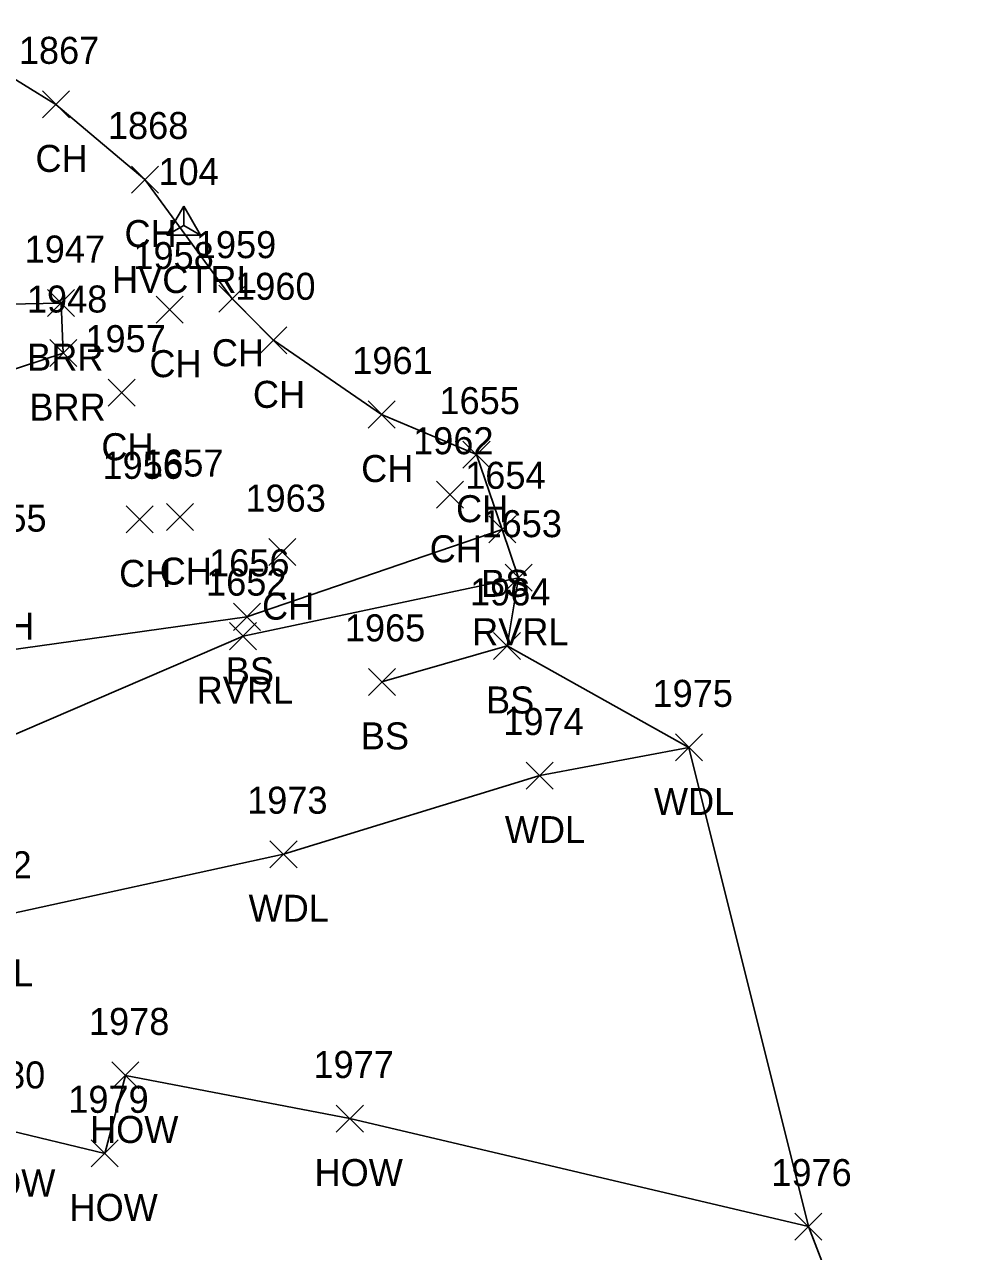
# Model space of a CAD drawing. Extents: x 1616726 to 1619875, y 273782 to 276557.
# Drawn here: x 1617145 to 1617213.9, y 276234.9 to 276325.7 of the extents above; entities that cross this region are included whole.
import ezdxf

# ---------------------------------------------------------------- set-up
doc = ezdxf.new("R2010")
doc.units = 0
for name, color, linetype in [('C_A', 7, 'Continuous'), ('C_I', 7, 'Continuous'), ('CPSM', 7, 'Continuous'), ('L_A', 7, 'Continuous'), ('L_I', 7, 'Continuous'), ('L_TIC', 7, 'Continuous'), ('LABL', 7, 'Continuous'), ('LAWA', 7, 'Continuous'), ('LAWE', 7, 'Continuous'), ('LBC', 7, 'Continuous'), ('LELB', 7, 'Continuous'), ('LSOGP', 7, 'Continuous')]:
    doc.layers.add(name, color=color, linetype=linetype)

msp = doc.modelspace()

# ---------------------------------------------------------------- linework, layer by layer
at = {"layer": 'CPSM'}
for p, q in [((1617155.513, 276310.096), (1617156.763, 276312.261)), ((1617155.513, 276310.096), (1617156.763, 276312.261)), ((1617158.013, 276310.096), (1617156.763, 276312.261)), ((1617156.763, 276310.817), (1617156.763, 276312.261)), ((1617158.013, 276310.096), (1617156.763, 276312.261)), ((1617156.763, 276310.817), (1617156.763, 276312.261)), ((1617155.513, 276310.096), (1617156.763, 276310.817)), ((1617155.513, 276310.096), (1617156.763, 276310.817)), ((1617155.513, 276310.096), (1617158.013, 276310.096)), ((1617155.513, 276310.096), (1617158.013, 276310.096)), ((1617156.763, 276310.817), (1617156.763, 276310.817)), ((1617156.763, 276310.817), (1617158.013, 276310.096)), ((1617156.763, 276310.817), (1617156.763, 276310.817)), ((1617156.763, 276310.817), (1617158.013, 276310.096))]:
    msp.add_line(p, q, dxfattribs=at)
at = {"layer": 'L_TIC'}
for points in [[(1617146.301, 276318.786), (1617148.301, 276320.786)], [(1617148.301, 276318.786), (1617146.301, 276320.786)], [(1617152.89, 276313.221), (1617154.89, 276315.221)], [(1617154.89, 276313.221), (1617152.89, 276315.221)], [(1617159.356, 276304.401), (1617161.356, 276306.401)], [(1617161.356, 276304.401), (1617159.356, 276306.401)], [(1617146.684, 276304.076), (1617148.684, 276306.076)], [(1617148.684, 276304.076), (1617146.684, 276306.076)], [(1617154.729, 276303.591), (1617156.729, 276305.591)], [(1617156.729, 276303.591), (1617154.729, 276305.591)], [(1617162.391, 276301.319), (1617164.391, 276303.319)], [(1617164.391, 276301.319), (1617162.391, 276303.319)], [(1617146.851, 276300.376), (1617148.851, 276302.376)], [(1617148.851, 276300.376), (1617146.851, 276302.376)], [(1617151.177, 276297.443), (1617153.177, 276299.443)], [(1617153.177, 276297.443), (1617151.177, 276299.443)], [(1617170.402, 276295.827), (1617172.402, 276297.827)], [(1617172.402, 276295.827), (1617170.402, 276297.827)], [(1617177.422, 276292.855), (1617179.422, 276294.855)], [(1617179.422, 276292.855), (1617177.422, 276294.855)], [(1617175.472, 276289.885), (1617177.472, 276291.885)], [(1617177.472, 276289.885), (1617175.472, 276291.885)], [(1617152.493, 276288.064), (1617154.493, 276290.064)], [(1617154.493, 276288.064), (1617152.493, 276290.064)], [(1617155.493, 276288.235), (1617157.493, 276290.235)], [(1617157.493, 276288.235), (1617155.493, 276290.235)], [(1617179.325, 276287.326), (1617181.325, 276289.326)], [(1617181.325, 276287.326), (1617179.325, 276289.326)], [(1617163.067, 276285.639), (1617165.067, 276287.639)], [(1617165.067, 276285.639), (1617163.067, 276287.639)], [(1617180.534, 276283.745), (1617182.534, 276285.745)], [(1617182.534, 276283.745), (1617180.534, 276285.745)], [(1617160.431, 276280.848), (1617162.431, 276282.848)], [(1617162.431, 276280.848), (1617160.431, 276282.848)], [(1617160.153, 276279.417), (1617162.153, 276281.417)], [(1617162.153, 276279.417), (1617160.153, 276281.417)], [(1617179.684, 276278.693), (1617181.684, 276280.693)], [(1617181.684, 276278.693), (1617179.684, 276280.693)], [(1617170.422, 276276.034), (1617172.422, 276278.034)], [(1617172.422, 276276.034), (1617170.422, 276278.034)], [(1617193.136, 276271.184), (1617195.136, 276273.184)], [(1617195.136, 276271.184), (1617193.136, 276273.184)], [(1617182.103, 276269.097), (1617184.103, 276271.097)], [(1617184.103, 276269.097), (1617182.103, 276271.097)], [(1617163.142, 276263.272), (1617165.142, 276265.272)], [(1617165.142, 276263.272), (1617163.142, 276265.272)], [(1617151.443, 276246.898), (1617153.443, 276248.898)], [(1617153.443, 276246.898), (1617151.443, 276248.898)], [(1617168.05, 276243.707), (1617170.05, 276245.707)], [(1617170.05, 276243.707), (1617168.05, 276245.707)], [(1617149.919, 276241.13), (1617151.919, 276243.13)], [(1617151.919, 276241.13), (1617149.919, 276243.13)], [(1617201.986, 276235.707), (1617203.986, 276237.707)], [(1617203.986, 276235.707), (1617201.986, 276237.707)]]:
    msp.add_lwpolyline(points, dxfattribs=at)
at = {"layer": 'LABL'}
msp.add_lwpolyline([(1617137.093, 276304.873), (1617147.684, 276305.076), (1617147.851, 276301.376), (1617132.471, 276296.326), (1617114.065, 276287.463)], dxfattribs=at)
at = {"layer": 'LAWA'}
msp.add_lwpolyline([(1617119.334, 276244.786), (1617142.251, 276259.493), (1617164.142, 276264.272), (1617183.103, 276270.097), (1617194.136, 276272.184)], dxfattribs=at)
at = {"layer": 'LAWE'}
msp.add_lwpolyline([(1617090.502, 276248.878), (1617102.367, 276255.855), (1617123.367, 276262.261), (1617141.244, 276271.864), (1617161.153, 276280.417), (1617181.534, 276284.745)], dxfattribs=at)
at = {"layer": 'LBC'}
msp.add_lwpolyline([(1617202.986, 276236.707), (1617169.05, 276244.707), (1617152.443, 276247.898), (1617150.919, 276242.13), (1617143.341, 276243.936)], dxfattribs=at)
at = {"layer": 'LELB'}
for points in [[(1617180.325, 276288.326), (1617161.431, 276281.848), (1617137.104, 276278.445), (1617120.409, 276268.034), (1617108.303, 276262.949), (1617094.244, 276258.017), (1617079.483, 276248.101), (1617068.225, 276247.781), (1617049.151, 276245.503), (1617035.056, 276240.813), (1617026.009, 276236.235), (1617014.974, 276241.9), (1616972.474, 276247.818), (1616960.605, 276245.765), (1616944.032, 276250.468), (1616920.652, 276257.271), (1616898.689, 276263.021), (1616845.503, 276278.094), (1616816.834, 276290.556), (1616792.378, 276296.226)], [(1617180.684, 276279.693), (1617171.422, 276277.034)]]:
    msp.add_lwpolyline(points, dxfattribs=at)
at = {"layer": 'LSOGP'}
msp.add_lwpolyline([(1617213.935, 276208.22), (1617202.986, 276236.707), (1617194.136, 276272.183), (1617180.684, 276279.693), (1617181.534, 276284.745), (1617180.325, 276288.326), (1617178.422, 276293.855), (1617171.402, 276296.826), (1617163.391, 276302.319), (1617160.356, 276305.401), (1617153.89, 276314.221), (1617147.301, 276319.786), (1617137.702, 276325.696)], dxfattribs=at)

# ---------------------------------------------------------------- texts
at = {"layer": 'C_A'}
msp.add_text('HVCTRL', height=2, dxfattribs=at).set_placement((1617151.456, 276305.817))
msp.add_text('HVCTRL', height=2, dxfattribs=at).set_placement((1617151.456, 276305.817))
at = {"layer": 'C_I'}
msp.add_text('104', height=2, dxfattribs=at).set_placement((1617154.889, 276313.817))
msp.add_text('104', height=2, dxfattribs=at).set_placement((1617154.889, 276313.817))
at = {"layer": 'L_A'}
for s, p in [('CH', (1617145.789, 276314.786)), ('CH', (1617152.378, 276309.221)), ('BRR', (1617145.172, 276300.076)), ('CH', (1617158.844, 276300.401)), ('CH', (1617154.217, 276299.591)), ('CH', (1617161.879, 276297.319)), ('BRR', (1617145.339, 276296.376)), ('CH', (1617150.665, 276293.443)), ('CH', (1617169.89, 276291.827)), ('CH', (1617176.91, 276288.855)), ('CH', (1617174.96, 276285.885)), ('CH', (1617151.981, 276284.064)), ('CH', (1617154.982, 276284.235)), ('BS', (1617178.766, 276283.326)), ('CH', (1617162.555, 276281.639)), ('CH', (1617141.843, 276280.156)), ('RVRL', (1617178.1, 276279.745)), ('BS', (1617159.872, 276276.848)), ('RVRL', (1617157.72, 276275.417)), ('BS', (1617179.125, 276274.693)), ('BS', (1617169.863, 276272.034)), ('WDL', (1617191.553, 276267.184)), ('WDL', (1617180.52, 276265.097)), ('WDL', (1617161.56, 276259.272)), ('WDL', (1617139.668, 276254.493)), ('HOW', (1617149.829, 276242.898)), ('HOW', (1617166.436, 276239.707)), ('HOW', (1617140.727, 276238.936)), ('HOW', (1617148.305, 276237.13))]:
    msp.add_text(s, height=2, dxfattribs=at).set_placement(p)
at = {"layer": 'L_I'}
for s, p in [('1867', (1617144.561, 276322.786)), ('1868', (1617151.15, 276317.221)), ('1947', (1617144.991, 276308.076)), ('1959', (1617157.655, 276308.401)), ('1958', (1617153.036, 276307.591)), ('1960', (1617160.564, 276305.319)), ('1948', (1617145.158, 276304.376)), ('1957', (1617149.484, 276301.443)), ('1961', (1617169.229, 276299.827)), ('1655', (1617175.682, 276296.855)), ('1962', (1617173.732, 276293.885)), ('1956', (1617150.745, 276292.064)), ('1657', (1617153.753, 276292.235)), ('1654', (1617177.585, 276291.326)), ('1963', (1617161.327, 276289.639)), ('1955', (1617140.662, 276288.156)), ('1653', (1617178.793, 276287.745)), ('1656', (1617158.636, 276284.848)), ('1652', (1617158.413, 276283.417)), ('1964', (1617177.944, 276282.693)), ('1965', (1617168.682, 276280.034)), ('1975', (1617191.443, 276275.184)), ('1974', (1617180.41, 276273.097)), ('1973', (1617161.45, 276267.272)), ('1972', (1617139.558, 276262.493)), ('1978', (1617149.75, 276250.898)), ('1977', (1617166.357, 276247.707)), ('1980', (1617140.562, 276246.936)), ('1979', (1617148.218, 276245.13)), ('1976', (1617200.238, 276239.707))]:
    msp.add_text(s, height=2, dxfattribs=at).set_placement(p)

doc.saveas('drawing.dxf')
